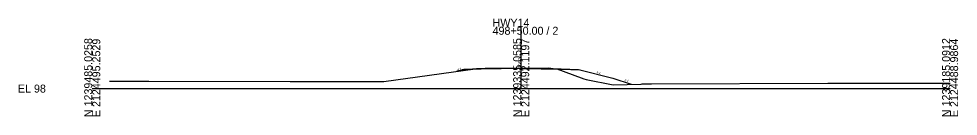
# Model space of a CAD drawing. Extents: x -26 to 303, y -10 to 11521.
# Drawn here: x -25.7 to 302.8, y 9990.3 to 10024.5 of the extents above; entities that cross this region are included whole.
import ezdxf

# ---------------------------------------------------------------- set-up
doc = ezdxf.new("R2010")
doc.units = 0
for name, color, linetype in [('XS_CELL', 7, 'Continuous'), ('XS_P_FINISHED_GRADE', 7, 'Continuous'), ('XS_P_SUBGRADE_GRANULAR', 7, 'Continuous'), ('XS_P_SUBGRADE_LEVELING', 7, 'Continuous'), ('XS_P_TX_FS_BS', 7, 'Continuous'), ('XS_X_GROUND', 7, 'Continuous'), ('XS_X_GROUND_TX', 7, 'Continuous')]:
    doc.layers.add(name, color=color, linetype=linetype)

msp = doc.modelspace()

# ---------------------------------------------------------------- linework, layer by layer
at = {"layer": 'XS_CELL'}
for p, q in [((150, 10000), (150, 10021.67)), ((0, 10000), (150, 10000)), ((150, 10000), (300, 10000))]:
    msp.add_line(p, q, dxfattribs=at)
at = {"layer": 'XS_P_FINISHED_GRADE'}
for p, q in [((150, 10007.21), (136, 10006.93)), ((150, 10007.21), (164, 10006.93)), ((130, 10006.69), (127.41, 10006.04)), ((136, 10006.93), (130, 10006.69)), ((164, 10006.93), (170, 10006.69)), ((170, 10006.69), (182, 10003.69)), ((182, 10003.69), (188.49, 10001.52))]:
    msp.add_line(p, q, dxfattribs=at)
at = {"layer": 'XS_P_SUBGRADE_GRANULAR'}
for p, q in [((136, 10006.8), (129.4, 10006.54)), ((164, 10006.8), (170.6, 10006.54))]:
    msp.add_line(p, q, dxfattribs=at)
at = {"layer": 'XS_P_SUBGRADE_LEVELING'}
for p, q in [((150, 10007.08), (136, 10006.8)), ((136, 10006.8), (136, 10006.93)), ((150, 10007.08), (164, 10006.8)), ((164, 10006.8), (164, 10006.93))]:
    msp.add_line(p, q, dxfattribs=at)
at = {"layer": 'XS_X_GROUND'}
for p, q in [((134.35, 10006.99), (137.46, 10007.19)), ((137.46, 10007.19), (144.12, 10007.19)), ((144.12, 10007.19), (150, 10007.21)), ((150, 10007.21), (159.55, 10007.22)), ((159.55, 10007.22), (161.23, 10007.03)), ((101.99, 10002.51), (133.87, 10006.93)), ((133.87, 10006.93), (134.35, 10006.99)), ((161.23, 10007.03), (162.5, 10006.88)), ((162.5, 10006.88), (171, 10003.74)), ((6.02, 10002.64), (19.84, 10002.6)), ((19.84, 10002.6), (69.25, 10002.47)), ((69.25, 10002.47), (94.27, 10002.44)), ((94.27, 10002.44), (101.99, 10002.51)), ((171, 10003.74), (171.91, 10003.41)), ((171.91, 10003.41), (172.78, 10003.24)), ((172.78, 10003.24), (182.19, 10001.37)), ((182.19, 10001.37), (191.94, 10001.6)), ((191.94, 10001.6), (192.36, 10001.62)), ((192.36, 10001.62), (195.61, 10001.63)), ((195.61, 10001.63), (257.23, 10001.89)), ((257.23, 10001.89), (284.38, 10001.92)), ((284.38, 10001.92), (300, 10001.93))]:
    msp.add_line(p, q, dxfattribs=at)

# ---------------------------------------------------------------- texts
at = {"layer": 'XS_CELL'}
for s, p in [('HWY14', (140, 10021.67)), ('498+50.00 / 2', (140, 10018.87)), ('EL 98', (-26, 9998.6))]:
    msp.add_text(s, height=2.8, dxfattribs=at).set_placement(p)
for s, p in [('N 1239485.0258', (0, 9990)), ('E 2124495.2529', (2.8, 9990)), ('N 1239335.0585', (150, 9990)), ('E 2124492.1197', (152.8, 9990)), ('N 1239185.0912', (300, 9990)), ('E 2124488.9864', (302.8, 9990))]:
    msp.add_text(s, height=2.8, rotation=90, dxfattribs=at).set_placement(p)
at = {"layer": 'XS_P_TX_FS_BS'}
for s, rotation, p in [('4:1', 14.0362, (127.74, 10006.22)), ('4:1', 345.9638, (176.25, 10005.39)), ('3:1', 341.5651, (186.02, 10002.72))]:
    msp.add_text(s, height=0.8, rotation=rotation, dxfattribs=at).set_placement(p)
at = {"layer": 'XS_X_GROUND_TX'}
msp.add_text('105.21', height=1, rotation=90, dxfattribs=at).set_placement((150, 10007.31))

doc.saveas('drawing.dxf')
